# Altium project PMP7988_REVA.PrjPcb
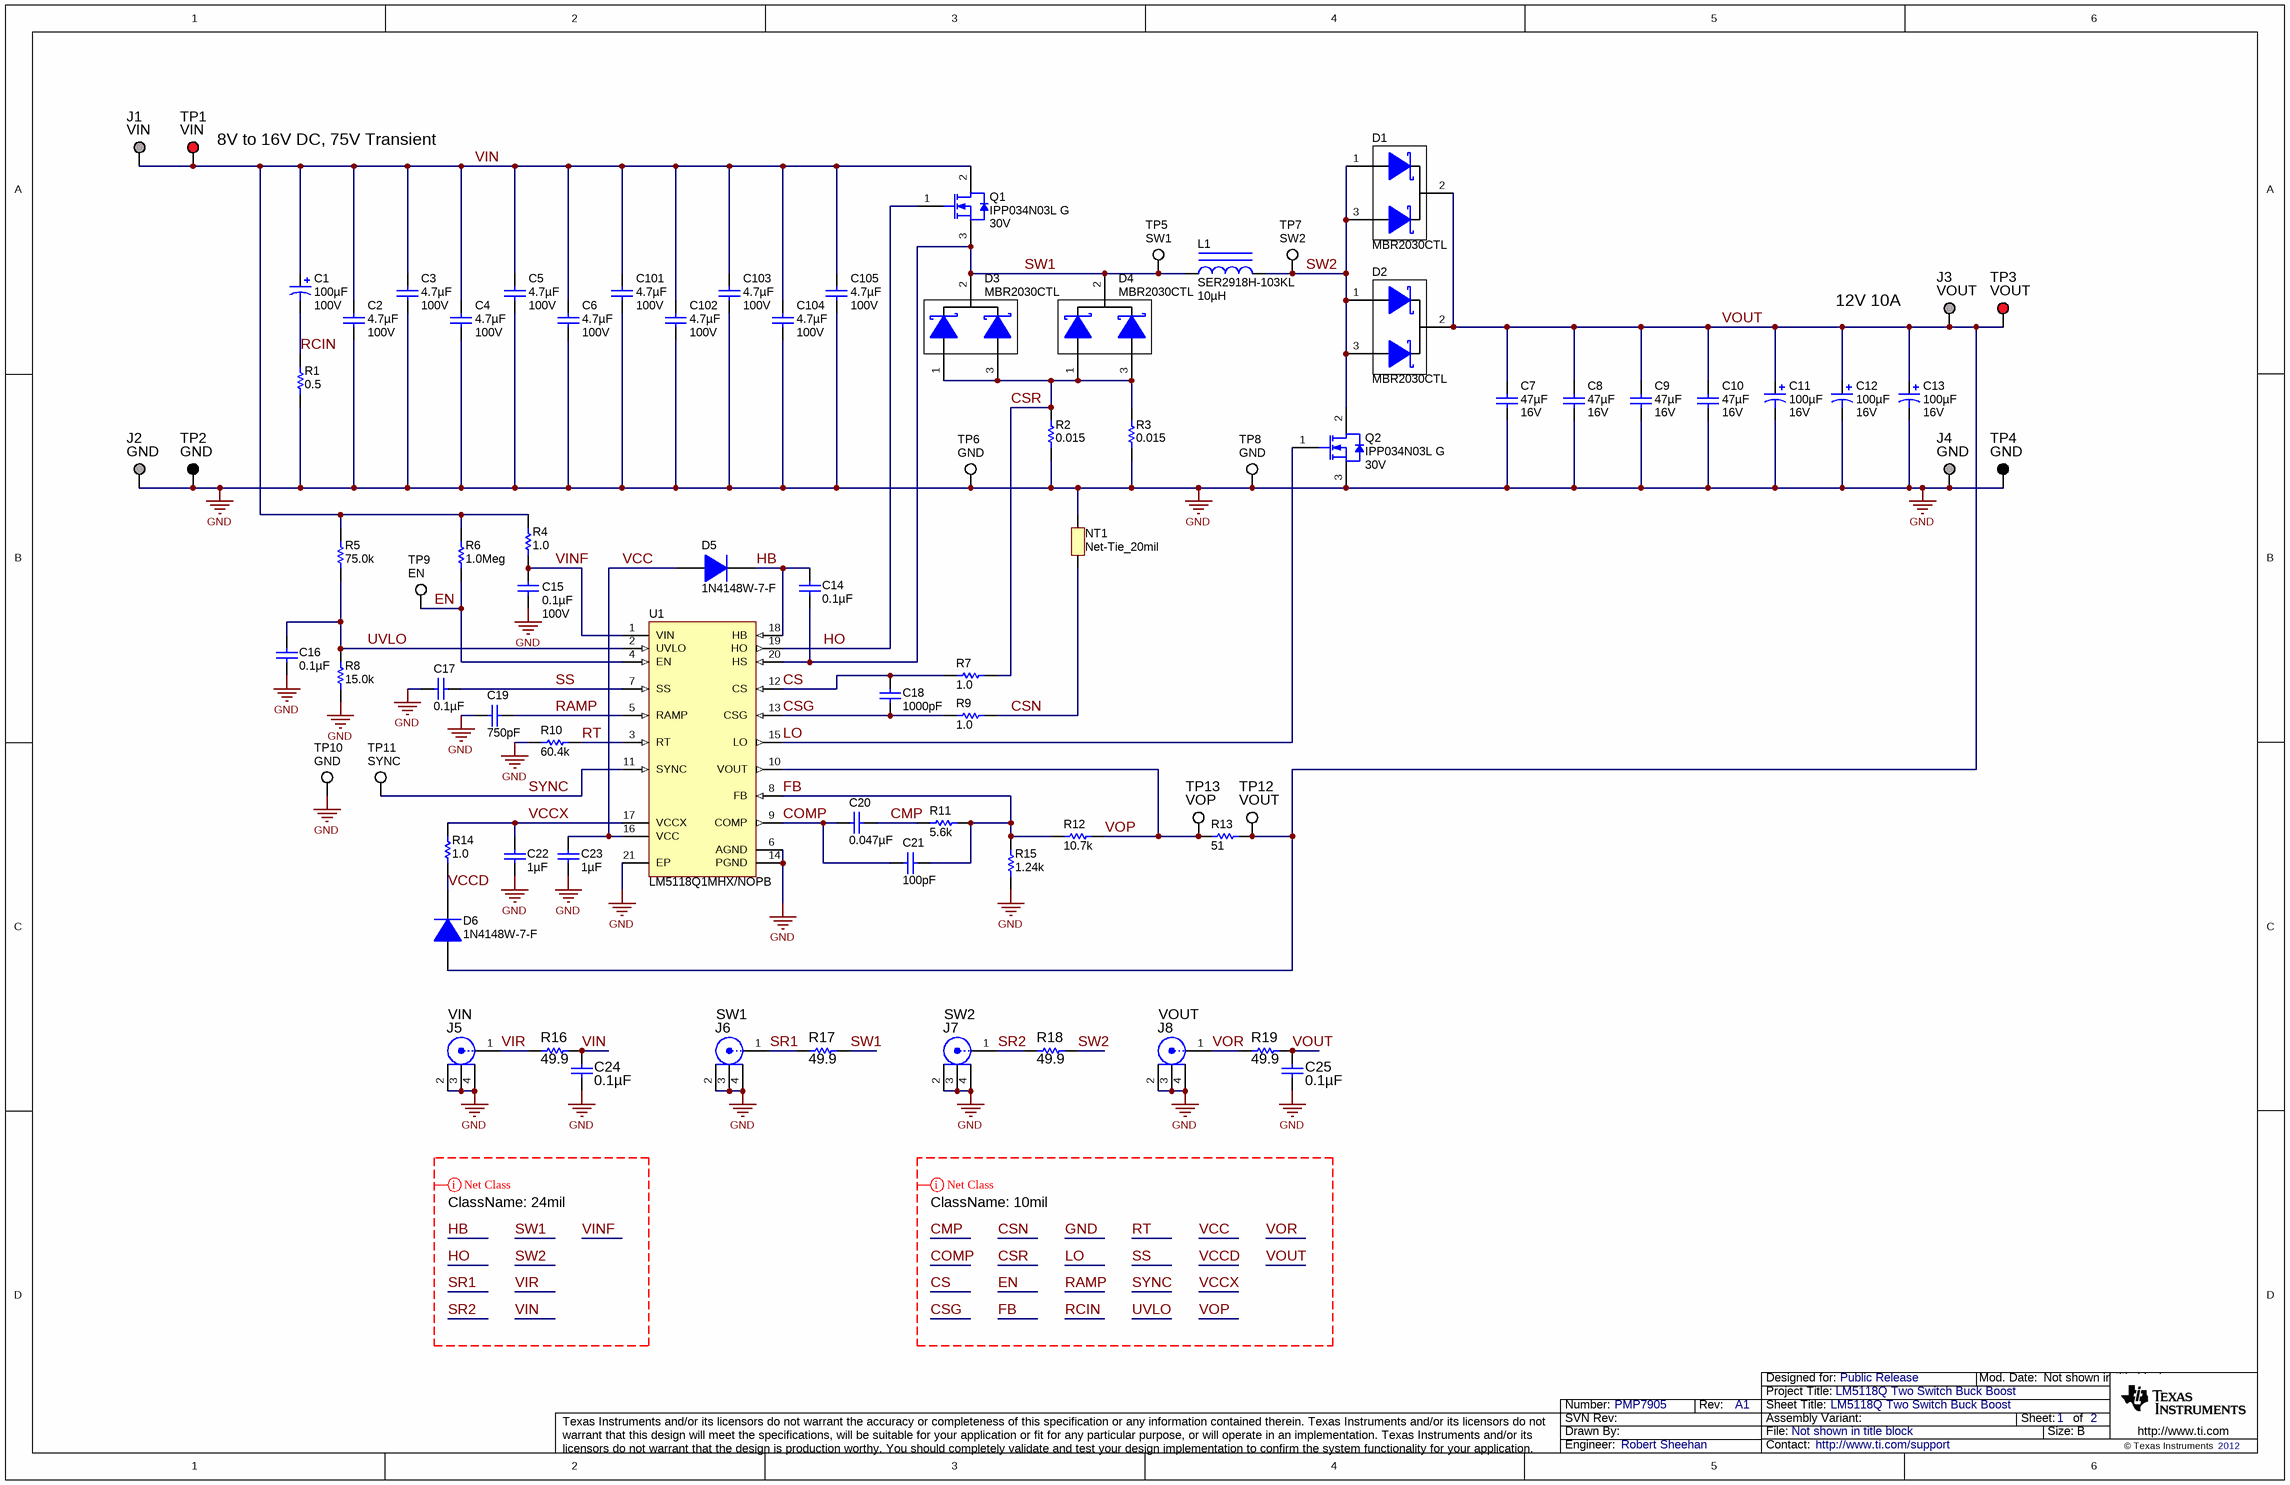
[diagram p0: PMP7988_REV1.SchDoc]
CopyrightYear: 2012; PCB_Layout: Robert Sheehan; PCB_Rev: A; PRJ_Customer: Public Release; PRJ_Engineer: Robert Sheehan; PRJ_Number: PMP7905; PRJ_Title: LM5118Q Two Switch Buck Boost; SCH_Rev: A1; TechSupport: http://www.ti.com/support
2 sheets, 118 parts. Net scope: global (net labels, ports and power ports of the same name join across sheets).
Board file: PMP7905_REVA.PcbDoc
Sheets:
  PMP7988_REV1.SchDoc
  PMP7988_REV1_Hardware.SchDoc

## Sheet PMP7988_REV1.SchDoc: LM5118Q Two Switch Buck Boost
size 431 x 279 mm; Date: Not shown in title block; ApprovedBy: Not shown in title block; CheckedBy: Not shown in title block; Author: Not shown in title block; CompanyName: Not shown in title block; Engineer: Not shown in title block; Organization: Not shown in title block; Address1: Not shown in title block; Address2: Not shown in title block; Address3: Not shown in title block; Address4: Not shown in title block; DocumentNumber: 1; Revision: Use project parameter SCH_Rev; SheetNumber: 1; SheetTotal: 2; PageSetup: Record=PageOptions|CenterHorizontal=True|CenterVertical=True|PrintScale=1.00|XCorrection=1.00|YCorrection=1.00|PrintKind=0|BorderSize=5000000|LeftOffset=0|BottomOffset=0|Orientation=2|PaperLength=1000|PaperWidth=1000|Scale=100|PaperSource=15|PrintQuality=600|MediaType=1|DitherType=10|PaperKind=Letter|PrintScaleMode=1

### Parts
C1  ValueDisplayed: 100µF  Value2: 100V  [SM_RADIAL_J16]  (hidden comment: EEV-FK2A101M)
C2  Value2: 100V  ValueDisplayed: 4.7µF  [1210]  (hidden comment: C3225X7S2A475M)
C3  Value2: 100V  ValueDisplayed: 4.7µF  [1210]  (hidden comment: C3225X7S2A475M)
C4  Value2: 100V  ValueDisplayed: 4.7µF  [1210]  (hidden comment: C3225X7S2A475M)
C5  Value2: 100V  ValueDisplayed: 4.7µF  [1210]  (hidden comment: C3225X7S2A475M)
C6  Value2: 100V  ValueDisplayed: 4.7µF  [1210]  (hidden comment: C3225X7S2A475M)
C7  ValueDisplayed: 47µF  Value2: 16V  [1210]  (hidden comment: GRM32ER61C476ME15L)
C8  ValueDisplayed: 47µF  Value2: 16V  [1210]  (hidden comment: GRM32ER61C476ME15L)
C9  ValueDisplayed: 47µF  Value2: 16V  [1210]  (hidden comment: GRM32ER61C476ME15L)
C10  ValueDisplayed: 47µF  Value2: 16V  [1210]  (hidden comment: GRM32ER61C476ME15L)
C11  ValueDisplayed: 100µF  Value2: 16V  [CAPSMT_62_F80]  (hidden comment: APXE160ARA101MF80G)
C12  ValueDisplayed: 100µF  Value2: 16V  [CAPSMT_62_F80]  (hidden comment: APXE160ARA101MF80G)
C13  ValueDisplayed: 100µF  Value2: 16V  [CAPSMT_62_F80]  (hidden comment: APXE160ARA101MF80G)
C14  ValueDisplayed: 0.1µF  [0805_HV]  (hidden comment: C2012X7R1E104K)
C15  ValueDisplayed: 0.1µF  Value2: 100V  [0805_HV]  (hidden comment: C2012X7R2A104K)
C16  ValueDisplayed: 0.1µF  [0805_HV]  (hidden comment: C2012X7R1E104K)
C17  ValueDisplayed: 0.1µF  [0805_HV]  (hidden comment: C2012X7R1E104K)
C18  ValueDisplayed: 1000pF  [0805_HV]  (hidden comment: GRM216R71E102KA01D)
C19  ValueDisplayed: 750pF  [0805_HV]  (hidden comment: GRM2165C1H751JA01D)
C20  ValueDisplayed: 0.047µF  [0805_HV]  (hidden comment: GRM219R71E473KA01D)
C21  ValueDisplayed: 100pF  [0805_HV]  (hidden comment: C2012C0G1H101J)
C22  ValueDisplayed: 1µF  [0805_HV]  (hidden comment: C2012X7R1E105K)
C23  ValueDisplayed: 1µF  [0805_HV]  (hidden comment: C2012X7R1E105K)
C24  ValueDisplayed: 0.1µF  [0805_HV]  (hidden comment: C2012X7R2A104K)
C25  ValueDisplayed: 0.1µF  [0805_HV]  (hidden comment: C2012X7R2A104K)
C101  Value2: 100V  ValueDisplayed: 4.7µF  [1210]  (hidden comment: C3225X7S2A475M)
C102  Value2: 100V  ValueDisplayed: 4.7µF  [1210]  (hidden comment: C3225X7S2A475M)
C103  Value2: 100V  ValueDisplayed: 4.7µF  [1210]  (hidden comment: C3225X7S2A475M)
C104  Value2: 100V  ValueDisplayed: 4.7µF  [1210]  (hidden comment: C3225X7S2A475M)
C105  Value2: 100V  ValueDisplayed: 4.7µF  [1210]  (hidden comment: C3225X7S2A475M)
D1  MBR2030CTL  [TO-220AB]
D2  MBR2030CTL  [TO-220AB]
D3  MBR2030CTL  [TO-220AB]
D4  MBR2030CTL  [TO-220AB]
D5  1N4148W-7-F  [SOD-123]
D6  1N4148W-7-F  [SOD-123]
J1  VIN  [Keystone1598-2]
J2  GND  [Keystone1598-2]
J3  VOUT  [Keystone1598-2]
J4  GND  [Keystone1598-2]
J5  VIN  [A-1JB]
J6  SW1  [A-1JB]
J7  SW2  [A-1JB]
J8  VOUT  [A-1JB]
L1  SER2918H-103KL  ValueDisplayed: 10µH  [SER2918]
NT1  Net-Tie_20mil  [Net-Tie_20mil]  (net tie, no BOM)
Q1  IPP034N03L G  value 30V  [TO-220AB]
Q2  IPP034N03L G  value 30V  [TO-220AB]
R1  value 0.5  [1206]  (hidden comment: CSR1206FKR500)
R2  value 0.015  [4527]  (hidden comment: WSR3R0150FEA)
R3  value 0.015  [4527]  (hidden comment: WSR3R0150FEA)
R4  value 1.0  [0805_HV]  (hidden comment: CRCW08051R00JNEA)
R5  value 75.0k  [0805_HV]  (hidden comment: CRCW080575K0FKEA)
R6  value 1.0Meg  [0805_HV]  (hidden comment: CRCW08051M00JNEA)
R7  value 1.0  [0805_HV]  (hidden comment: CRCW08051R00JNEA)
R8  value 15.0k  [0805_HV]  (hidden comment: CRCW080515K0FKEA)
R9  value 1.0  [0805_HV]  (hidden comment: CRCW08051R00JNEA)
R10  value 60.4k  [0805_HV]  (hidden comment: CRCW080560K4FKEA)
R11  value 5.6k  [0805_HV]  (hidden comment: CRCW08055K60JNEA)
R12  value 10.7k  [0805_HV]  (hidden comment: CRCW080510K7FKEA)
R13  value 51  [0805_HV]  (hidden comment: CRCW080551R0JNEA)
R14  value 1.0  [0805_HV]  (hidden comment: CRCW08051R00JNEA)
R15  value 1.24k  [0805_HV]  (hidden comment: CRCW08051K24FKEA)
R16  value 49.9  [0805_HV]  (hidden comment: CRCW080549R9FKEA)
R17  value 49.9  [0805_HV]  (hidden comment: CRCW080549R9FKEA)
R18  value 49.9  [0805_HV]  (hidden comment: CRCW080549R9FKEA)
R19  value 49.9  [0805_HV]  (hidden comment: CRCW080549R9FKEA)
TP1  VIN  [Keystone5010]
TP2  GND  [Keystone5011]
TP3  VOUT  [Keystone5010]
TP4  GND  [Keystone5011]
TP5  SW1  [Testpoint_Keystone_Miniature]
TP6  GND  [Testpoint_Keystone_Miniature]
TP7  SW2  [Testpoint_Keystone_Miniature]
TP8  GND  [Testpoint_Keystone_Miniature]
TP9  EN  [Testpoint_Keystone_Miniature]
TP10  GND  [Testpoint_Keystone_Miniature]
TP11  SYNC  [Testpoint_Keystone_Miniature]
TP12  VOUT  [Keystone5012]
TP13  VOP  [Keystone5012]
U1  LM5118Q1MHX/NOPB  [MXA20A_N]

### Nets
GND: C2.2 C3.2 C4.2 C5.2 C6.2 C7.2 C8.2 C9.2 C10.2 C11.2(-) C12.2(-) C13.2(-) C15.2 C16.2 C17.1 C19.1 C22.2 C23.2 C24.2 C25.2 C101.2 C102.2 C103.2 C104.2 C105.2 J2.1 J4.1 J5.2 J5.3 J5.4 J6.2 J6.3 J6.4 J7.2 J7.3 J7.4 J8.2 J8.3 J8.4 NT1.1 Q2.3(S) R1.1 R2.1 R3.1 R8.1 R10.2 R15.1 TP2.1 TP4.1 TP6.1 TP8.1 TP10.1 U1.6(AGND) U1.14(PGND) U1.21(EP)
CMP: C20.1 R11.1
COMP: C20.2 C21.2 U1.9(COMP)
CS: C18.1 R7.2 U1.12(CS)
CSG: C18.2 R9.2 U1.13(CSG)
CSN: NT1.2 R9.1
CSR: D3.1(A) D3.3(A) D4.1(A) D4.3(A) R2.2 R3.2 R7.1
EN: R6.1 TP9.1 U1.4(EN)
FB: C21.1 R11.2 R12.1 R15.2 U1.8(FB)
HB: C14.1 D5.1(K) U1.18(HB)
HO: Q1.1(G) U1.19(HO)
LO: Q2.1(G) U1.15(LO)
RAMP: C19.2 U1.5(RAMP)
RCIN: C1.2(-) R1.2
RT: R10.1 U1.3(RT)
SR1: J6.1 R17.1
SR2: J7.1 R18.1
SS: C17.2 U1.7(SS)
SW1: C14.2 D3.2(K) D4.2(K) L1.2 Q1.3(S) R17.2 TP5.1 U1.20(HS)
SW2: D1.1(A) D1.3(A) D2.1(A) D2.3(A) L1.1 Q2.2(D) R18.2 TP7.1
SYNC: TP11.1 U1.11(SYNC)
UVLO: C16.1 R5.1 R8.2 U1.2(UVLO)
VCC: C23.1 D5.2(A) U1.16(VCC)
VCCD: D6.1(K) R14.2
VCCX: C22.1 R14.1 U1.17(VCCX)
VIN: C1.1(+) C2.1 C3.1 C4.1 C5.1 C6.1 C24.1 C101.1 C102.1 C103.1 C104.1 C105.1 J1.1 Q1.2(D) R4.1 R5.2 R6.2 R16.2 TP1.1
VINF: C15.1 R4.2 U1.1(VIN)
VIR: J5.1 R16.1
VOP: R12.2 R13.1 TP13.1 U1.10(VOUT)
VOR: J8.1 R19.1
VOUT: C7.1 C8.1 C9.1 C10.1 C11.1(+) C12.1(+) C13.1(+) C25.1 D1.2(K) D2.2(K) D6.2(A) J3.1 R13.2 R19.2 TP3.1 TP12.1

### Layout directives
net class 24mil: HB, HO, SR1, SR2, SW1, SW2, VIN, VINF, VIR
net class 10mil: CMP, COMP, CS, CSG, CSN, CSR, EN, FB, GND, LO, RAMP, RCIN, RT, SS, SYNC, UVLO, VCC, VCCD, VCCX, VOP, VOR, VOUT

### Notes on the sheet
- (near TP1) 8V to 16V DC, 75V Transient
- (near J3) 12V 10A

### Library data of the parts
C1 = EEV-FK2A101M: CAP, AL, 100uF, 100V, +/-20%, 0.17 ohm, SMD; Manufacturer: Panasonic; Polarized: Y; CompType: Capacitor; U/M: EA; Cap_F: 0.0001; Tolerance_%: 20; VDC_V: 100; ESR_Ohm: 0.17; IRMS_A: 0.793; TaMin_C: -55; TaMax_C: 105; Cap_Case: J16
C2-C6 C101-C105 = C3225X7S2A475M: CAP, CERM, 4.7uF, 100V, +/-20%, X7S, 1210; Manufacturer: TDK; Polarized: N; CompType: Capacitor; U/M: EA; Cap_F: 0.0000047; Tolerance_%: 20; VDC_V: 100; TaMin_C: -55; TaMax_C: 125
C7-C10 = GRM32ER61C476ME15L: CAP, CERM, 47uF, 16V, +/-20%, X5R, 1210; Manufacturer: MuRata; Polarized: N; CompType: Capacitor; U/M: EA; Cap_F: 0.000047; Tolerance_%: 20; ESR_Ohm: 0.002; Value1: 0.002 ohm; VDC_V: 16; TaMin_C: -55; TaMax_C: 85
C11-C13 = APXE160ARA101MF80G: CAP, AL, 100uF, 16V, +/-20%, 0.024 ohm, SMD; Manufacturer: Nippon Chemi-Con; Polarized: Y; CompType: Capacitor; U/M: EA; Cap_F: 0.0001; Tolerance_%: 20; VDC_V: 16; ESR_Ohm: 0.024; IRMS_A: 2.7; TaMin_C: -55; TaMax_C: 105; Cap_Case: F80
C14 C16 C17 = C2012X7R1E104K: CAP, CERM, 0.1uF, 25V, +/-10%, X7R, 0805; Manufacturer: TDK; Polarized: N; CompType: Capacitor; U/M: EA; Cap_F: 0.0000001; Tolerance_%: 10; VDC_V: 25; TaMin_C: -55; TaMax_C: 125; Cap_Case: 0805
C15 = C2012X7R2A104K: CAP, CERM, 0.1uF, 100V, +/-10%, X7R, 0805; Manufacturer: TDK; Polarized: N; CompType: Capacitor; U/M: EA; Cap_F: 0.0000001; Tolerance_%: 10; ESR_Ohm: 0.0158; Value1: 0.0158 ohm; VDC_V: 100; TaMin_C: -55; TaMax_C: 125; Cap_Case: 0805
C18 = GRM216R71E102KA01D: CAP, CERM, 1000pF, 25V, +/-10%, X7R, 0805; Manufacturer: MuRata; Polarized: N; CompType: Capacitor; U/M: EA; Cap_F: 0.000000001; Tolerance_%: 10; VDC_V: 25; TaMin_C: -55; TaMax_C: 125; Cap_Case: 0805
C19 = GRM2165C1H751JA01D: CAP, CERM, 750pF, 50V, +/-5%, C0G/NP0, 0805; Manufacturer: MuRata; Polarized: N; CompType: Capacitor; U/M: EA; Cap_F: 0.00000000075; Tolerance_%: 5; VDC_V: 50; TaMin_C: -55; TaMax_C: 125; Cap_Case: 0805
C20 = GRM219R71E473KA01D: CAP, CERM, 0.047uF, 25V, +/-10%, X7R, 0805; Manufacturer: MuRata; Polarized: N; CompType: Capacitor; U/M: EA; Cap_F: 0.000000047; Tolerance_%: 10; VDC_V: 25; TaMin_C: -55; TaMax_C: 125; Cap_Case: 0805
C21 = C2012C0G1H101J: CAP, CERM, 100pF, 50V, +/-5%, C0G/NP0, 0805; Manufacturer: TDK; Polarized: N; CompType: Capacitor; U/M: EA; Cap_F: 0.0000000001; Tolerance_%: 5; VDC_V: 50; TaMin_C: -55; TaMax_C: 125; Cap_Case: 0805
C22 C23 = C2012X7R1E105K: CAP, CERM, 1uF, 25V, +/-10%, X7R, 0805; Manufacturer: TDK; Polarized: N; CompType: Capacitor; U/M: EA; Cap_F: 0.000001; Tolerance_%: 10; ESR_Ohm: 0.0075; Value1: 0.0075 ohm; VDC_V: 25; TaMin_C: -55; TaMax_C: 125; Cap_Case: 0805
C24 C25 = C2012X7R2A104K: CAP, CERM, 0.1uF, 100V, +/-10%, X7R, 0805; Manufacturer: TDK; Cap_Case: 0805; ESR_Ohm: 0.0158; Polarized: N; TaMax_C: 125; TaMin_C: -55; Tolerance_%: 10; VDC_V: 100; Cap_F: 0.0000001; CompType: Capacitor; Value1: 0.0158 ohm; U/M: EA
D1-D4 = MBR2030CTL: Diode, Schottky, 30V, 20A, TO-220; Manufacturer: On Semiconductor; Value: 0.52V; U/M: EA; Vf_V: 0.52; Io_A: 15; Vr_V: 30; TJmax_C: 150; RJC_CperW: 3
D5 D6 = 1N4148W-7-F: Diode, Ultrafast, 100V, 0.15A, SOD-123; Manufacturer: Diodes Inc.; U/M: EA; Vf_V: 1.25; Io_A: 0.15; Vr_V: 100; TJmax_C: 150; Value: 1.25V
J1-J4 = 1598-2: Terminal, Turret, TH, Triple; Manufacturer: Keystone; Alternate PartNumber: Equivalent; Alternate Manufacturer: Any; CompType: Turret Terminal; U/M: EA
J5-J8 = A-1JB: Connector, RF Jack, Vertical, Gold, SMD; Manufacturer: Amphenol; SymbolCreator: crossc; U/M: EA; Value: 50 ohm
L1 = SER2918H-103KL: Inductor, Shielded E Core, Ferrite, 10uH, 28A, 0.0026 ohm, SMD; Manufacturer: Coilcraft; Ind_H: 10.0E-6; Imax_A: 28; Irms: 28A @ 40C rise; Isat: 32.1A @ 30% inductance drop; DCR_ohm: 0.0026; U/M: EA
NT1 = Net-Tie_20mil: Single point connection between nets.; SymbolCreator: crossc
Q1 Q2 = IPP034N03L G: MOSFET, N-CH, 30V, 80A, TO-220; Manufacturer: Infineon Technologies; Alternate Manufacturer: None; U/M: EA; ChType: N; VdsMax_V: 30; Value1: 0.0034 ohm; Rdson45_Ohm: 0.0038; Value2: 25 nC; QgTyp_nC: 25; Vgs_V: 20; IdsMax_A: 120
R1 = CSR1206FKR500: RES, 0.5 ohm, 1%, 0.5W, 1206; Manufacturer: Stackpole Electronics Inc; CompType: Resistor; Value_Code: R500; Tolerance_%: 1; TempCo: 100 ppm/C; U/M: EA
R2 R3 = WSR3R0150FEA: RES, 0.015 ohm, 1%, 3W, 4527; Manufacturer: Vishay-Dale; CompType: Resistor; Value_Code: R015; Tolerance_%: 1; Power_W: 3; TempCo: 75 ppm/C; EIA_Code: E96; U/M: EA
R4 R7 R9 R14 = CRCW08051R00JNEA: RES, 1.0 ohm, 5%, 0.125W, 0805; Manufacturer: Vishay-Dale; CompType: Resistor; Res_ohm: 1; Value_Code: 1R00; Tolerance_%: 5; Power_W: 0.125; VDC_V: 150; TempCo: 200 ppm/C; EIA_Code: E24; U/M: EA
R5 = CRCW080575K0FKEA: RES, 75.0k ohm, 1%, 0.125W, 0805; Manufacturer: Vishay-Dale; CompType: Resistor; Res_ohm: 75000; Value_Code: 75k0; Tolerance_%: 1; Power_W: 0.125; VDC_V: 150; TempCo: 100 ppm/C; EIA_Code: E96; U/M: EA
R6 = CRCW08051M00JNEA: RES, 1.0Meg ohm, 5%, 0.125W, 0805; Manufacturer: Vishay-Dale; CompType: Resistor; Res_ohm: 1000000; Value_Code: 1M00; Tolerance_%: 5; Power_W: 0.125; VDC_V: 150; TempCo: 200 ppm/C; EIA_Code: E24; U/M: EA
R8 = CRCW080515K0FKEA: RES, 15.0k ohm, 1%, 0.125W, 0805; Manufacturer: Vishay-Dale; CompType: Resistor; Res_ohm: 15000; Value_Code: 15k0; Tolerance_%: 1; Power_W: 0.125; VDC_V: 150; TempCo: 100 ppm/C; EIA_Code: E96; U/M: EA
R10 = CRCW080560K4FKEA: RES, 60.4k ohm, 1%, 0.125W, 0805; Manufacturer: Vishay-Dale; CompType: Resistor; Res_ohm: 60400; Value_Code: 60k4; Tolerance_%: 1; Power_W: 0.125; VDC_V: 150; TempCo: 100 ppm/C; EIA_Code: E96; U/M: EA
R11 = CRCW08055K60JNEA: RES, 5.6k ohm, 5%, 0.125W, 0805; Manufacturer: Vishay-Dale; CompType: Resistor; Res_ohm: 5600; Value_Code: 5k60; Tolerance_%: 5; Power_W: 0.125; VDC_V: 150; TempCo: 200 ppm/C; EIA_Code: E24; U/M: EA
R12 = CRCW080510K7FKEA: RES, 10.7k ohm, 1%, 0.125W, 0805; Manufacturer: Vishay-Dale; CompType: Resistor; Res_ohm: 10700; Value_Code: 10k7; Tolerance_%: 1; Power_W: 0.125; VDC_V: 150; TempCo: 100 ppm/C; EIA_Code: E96; U/M: EA
R13 = CRCW080551R0JNEA: RES, 51 ohm, 5%, 0.125W, 0805; Manufacturer: Vishay-Dale; CompType: Resistor; Value_Code: 51R0; Tolerance_%: 5; Power_W: 0.125; VDC_V: 150; TempCo: 200 ppm/C; EIA_Code: E24; U/M: EA
R15 = CRCW08051K24FKEA: RES, 1.24k ohm, 1%, 0.125W, 0805; Manufacturer: Vishay-Dale; CompType: Resistor; Res_ohm: 1240; Value_Code: 1k24; Tolerance_%: 1; Power_W: 0.125; VDC_V: 150; TempCo: 100 ppm/C; EIA_Code: E96; U/M: EA
R16-R19 = CRCW080549R9FKEA: RES, 49.9 ohm, 1%, 0.125W, 0805; Manufacturer: Vishay-Dale; Alternate PartNumber: Equivalent; Alternate Manufacturer: Any; CompType: Resistor; Value_Code: 49R9; Tolerance_%: 1; Power_W: 0.125; VDC_V: 150; TempCo: 100 ppm/C; EIA_Code: E96; U/M: EA
TP1 TP3 = 5010: Test Point, TH, Multipurpose, Red; Manufacturer: Keystone; Alternate Manufacturer: Any; Alternate PartNumber: Equivalent; CompType: Test Point Loop; U/M: EA
TP2 TP4 = 5011: Test Point, TH, Multipurpose, Black; Manufacturer: Keystone; Alternate Manufacturer: Any; Alternate PartNumber: Equivalent; CompType: Test Point Loop; U/M: EA
TP5-TP11 = 5015: Test Point, SMT, Miniature; Manufacturer: Keystone; CompType: Test Point Loop; U/M: EA
TP12 TP13 = 5012: Test Point, TH, Multipurpose, White; Manufacturer: Keystone; Alternate Manufacturer: Any; Alternate PartNumber: Equivalent; CompType: Test Point Loop; U/M: EA
U1 = LM5118Q1MHX/NOPB: Wide Voltage Range Buck-Boost Controller, 20-pin TSSOP-EP, Pb-Free; Manufacturer: National Semiconductor; PackageTopMarking: NSUZXYTT*LM5118*Q1MH; PowerWise: N; CompType: Switcher

## Sheet PMP7988_REV1_Hardware.SchDoc: LM5118Q Two Switch Buck Boost Hardware
size 431 x 279 mm; Date: Not shown in title block; ApprovedBy: Not shown in title block; CheckedBy: Not shown in title block; Author: Not shown in title block; CompanyName: Not shown in title block; Engineer: Not shown in title block; Organization: Not shown in title block; Address1: Not shown in title block; Address2: Not shown in title block; Address3: Not shown in title block; Address4: Not shown in title block; DocumentNumber: 2; Revision: Use project parameter SCH_Rev; SheetNumber: 2; SheetTotal: 2; PageSetup: Record=PageOptions|CenterHorizontal=True|CenterVertical=True|PrintScale=1.00|XCorrection=1.00|YCorrection=1.00|PrintKind=0|BorderSize=5000000|LeftOffset=0|BottomOffset=0|Orientation=2|PaperLength=1000|PaperWidth=1000|Scale=100|PaperSource=15|PrintQuality=600|MediaType=1|DitherType=10|PaperKind=Letter|PrintScaleMode=1
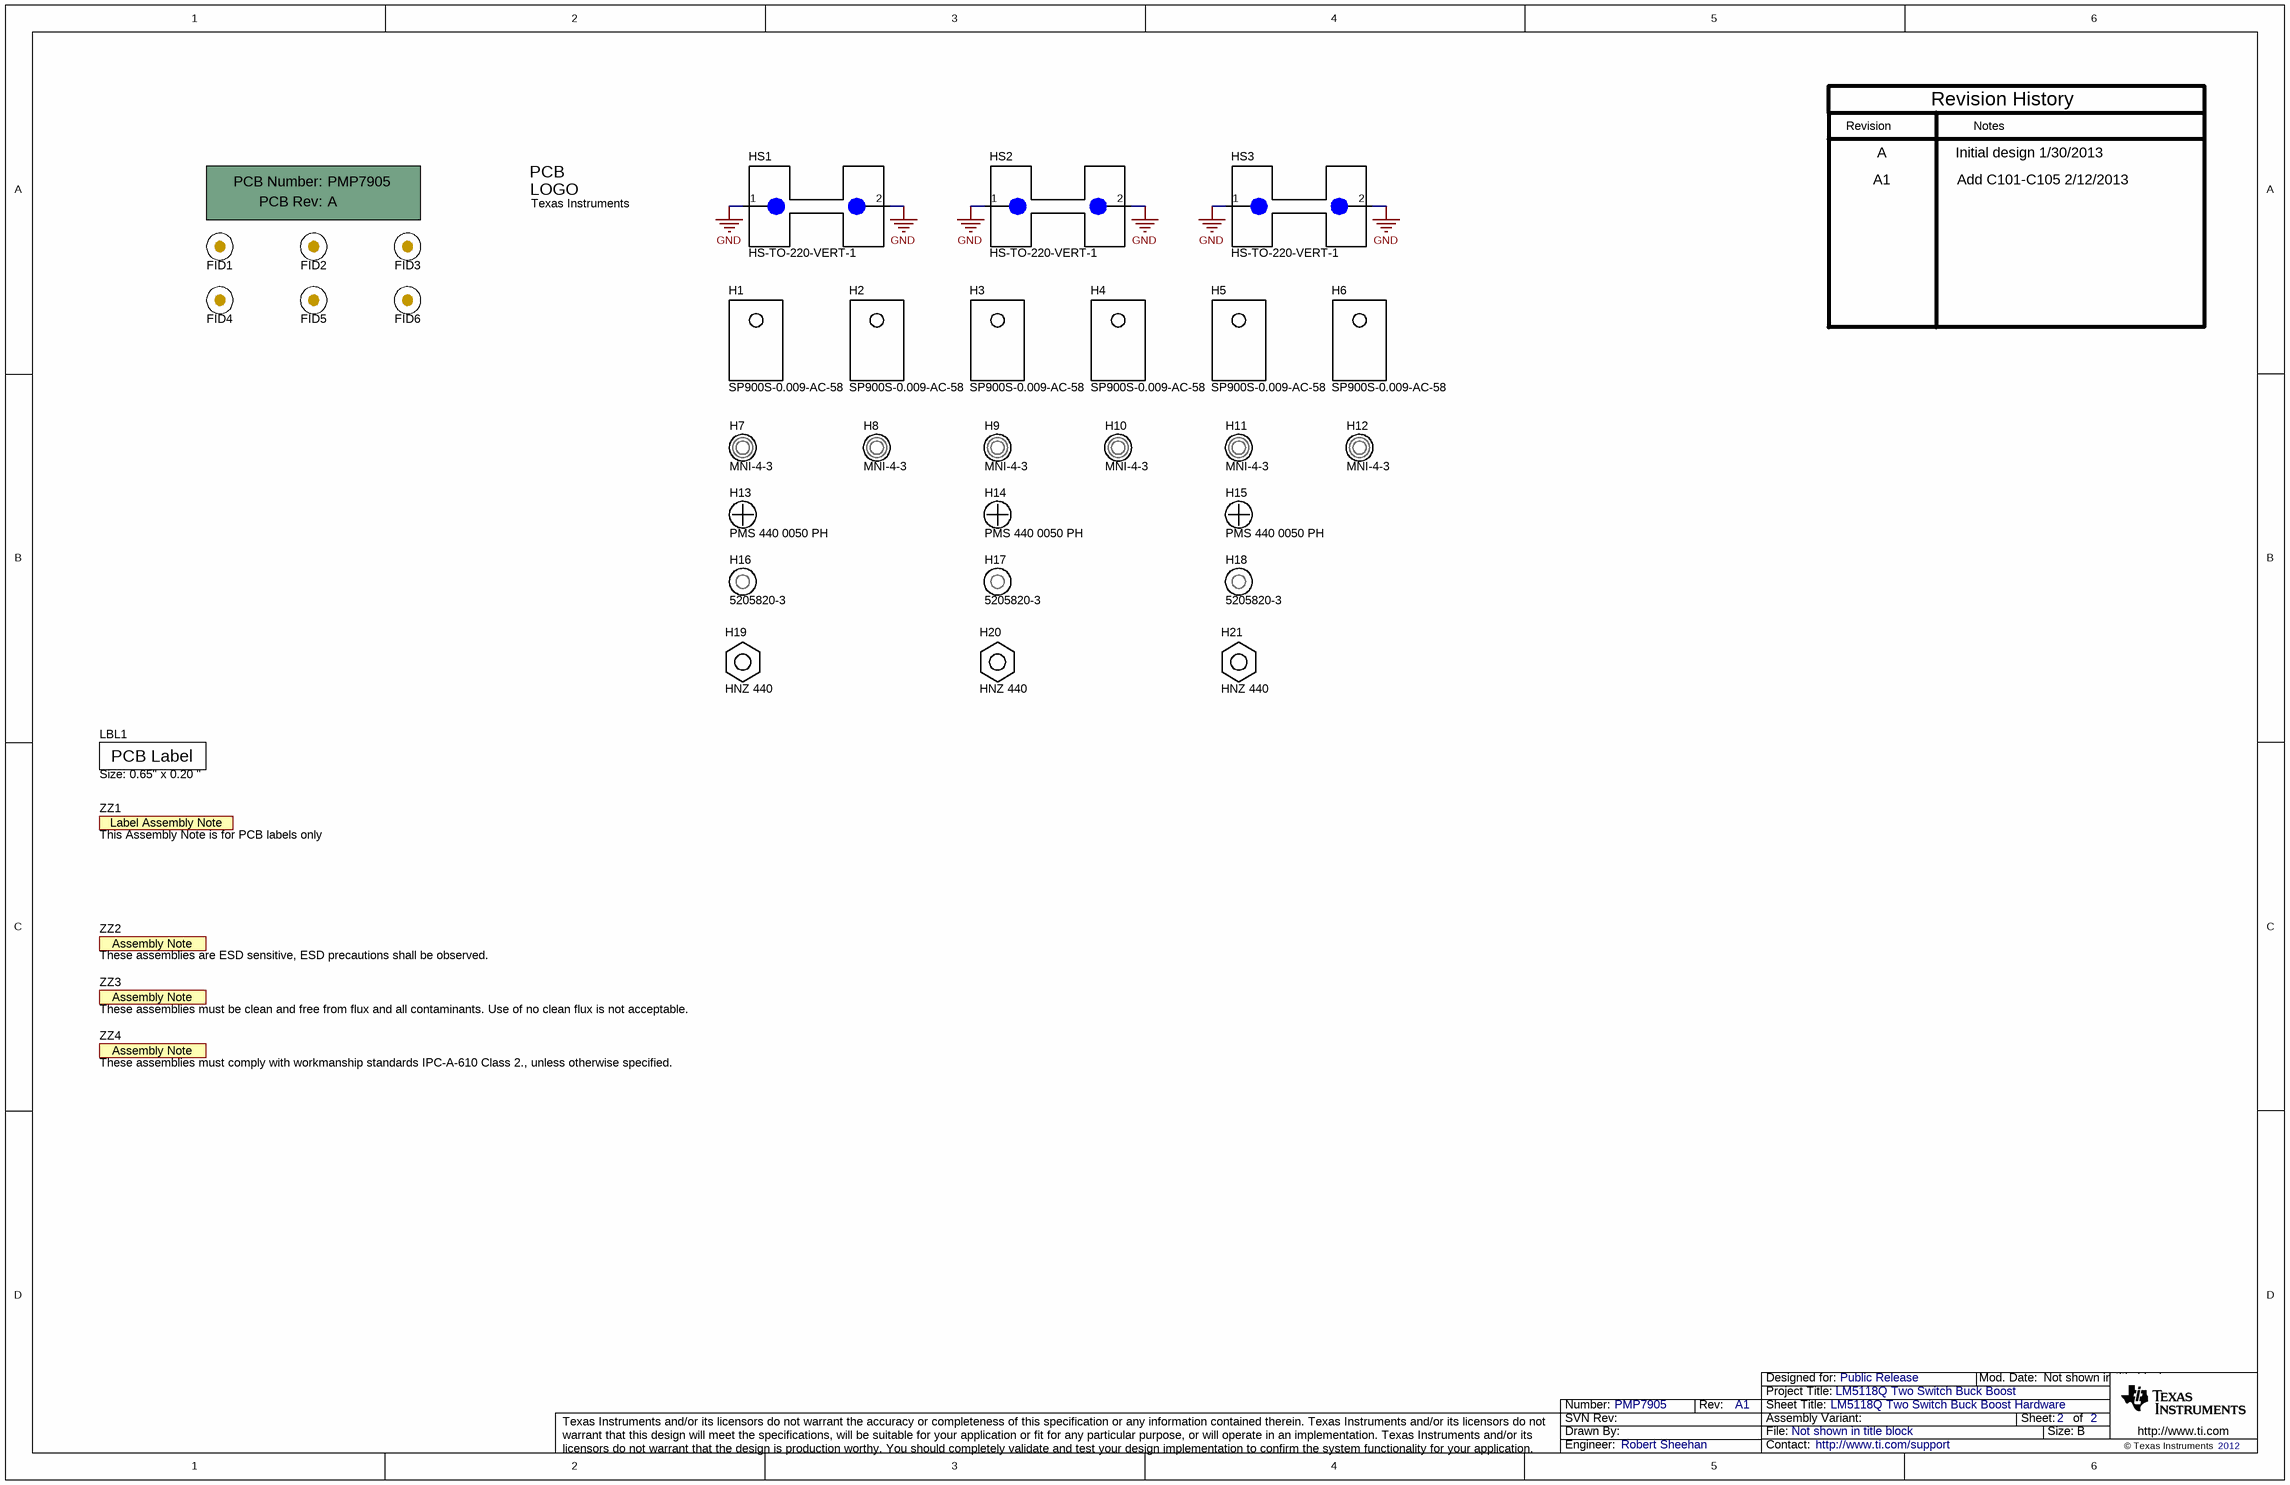
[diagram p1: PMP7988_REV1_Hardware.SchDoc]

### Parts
!PCB1  Printed Circuit Board  (value not drawn)  (mechanical)
FID1  Fiducial  [Fiducial10-20_TopLayerKeepOutOnly]  (value not drawn)
FID2  Fiducial  [Fiducial10-20_TopLayerKeepOutOnly]  (value not drawn)
FID3  Fiducial  [Fiducial10-20_TopLayerKeepOutOnly]  (value not drawn)
FID4  Fiducial  [Fiducial10-20_TopLayerKeepOutOnly]  (value not drawn)
FID5  Fiducial  [Fiducial10-20_TopLayerKeepOutOnly]  (value not drawn)
FID6  Fiducial  [Fiducial10-20_TopLayerKeepOutOnly]  (value not drawn)
H1  SP900S-0.009-AC-58
H2  SP900S-0.009-AC-58
H3  SP900S-0.009-AC-58
H4  SP900S-0.009-AC-58
H5  SP900S-0.009-AC-58
H6  SP900S-0.009-AC-58
H7  MNI-4-3
H8  MNI-4-3
H9  MNI-4-3
H10  MNI-4-3
H11  MNI-4-3
H12  MNI-4-3
H13  PMS 440 0050 PH
H14  PMS 440 0050 PH
H15  PMS 440 0050 PH
H16  5205820-3
H17  5205820-3
H18  5205820-3
H19  HNZ 440
H20  HNZ 440
H21  HNZ 440
HS1  HS-TO-220-VERT-1  [HS-TO-220-VERT-1]
HS2  HS-TO-220-VERT-1  [HS-TO-220-VERT-1]
HS3  HS-TO-220-VERT-1  [HS-TO-220-VERT-1]
LBL1  Size: 0.65" x 0.20 "  [Label_650x200]
Logo1  Texas Instruments  [TI_Stacked_SolderMask_Small]  (no BOM)
ZZ1  This Assembly Note is for PCB labels only  [AssemblyNoteLabel]  (no BOM)
ZZ2  These assemblies are ESD sensitive, ESD precautions shall be observed.  [AssemblyNote]  (no BOM)
ZZ3  These assemblies must be clean and free from flux and all contaminants. Use of no clean flux is not acceptable.  [AssemblyNote]  (no BOM)
ZZ4  These assemblies must comply with workmanship standards IPC-A-610 Class 2., unless otherwise specified.  [AssemblyNote]  (no BOM)

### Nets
GND: HS1.1 HS1.2 HS2.1 HS2.2 HS3.1 HS3.2

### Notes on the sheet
- Revision History
- Revision
- A
- Notes
- Initial design 1/30/2013
- A1
- Add C101-C105 2/12/2013

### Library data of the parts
!PCB1 = PCB: Manufacturer: Any; PartNumber: PMP7905; SymbolCreator: a0412235
FID1-FID6 = Fiducial: Fiducial mark.  There is nothing to buy or mount.; SymbolCreator: codlsc
H1-H6 = Sil-Pad-TO-220: THERM PAD TO-220 W/ADH .009" SP9; Manufacturer: Bergquist; CompType: Hardware; U/M: EA; Shape: Rectangular; Outline: 19.05mm x 12.70mm; Adhesive: Adhesive - One Side; Backing, Carrier: Fiberglass; Thermal Resistivity: 0.61°C/W; Thermal Conductivity: 1.6 W/m-K
H7-H12 = Shoulder-Washer-TO-220: WASHER SHOULDER #4 NYLON 25/PK; Manufacturer: Richco Plastic Co; CompType: Hardware
H13-H15 = Screw#4-40x1/2: Machine Screw, Round, #4-40 x 1/2 Steel, Philips panhead; Manufacturer: B&F Fastener Supply; CompType: Hardware; U/M: EA; Description: MACHINE SCREW PAN PHILLIPS 4-40; Drive Type: Phillips; Thread Size: 4-40; Head Height: 0.075" (1.91mm); Plating: Zinc
H16-H18 = Washer#4: WASHER FLAT #4 STEEL; Manufacturer: TE Connectivity; CompType: Hardware; Plating: Zinc, Clear Chromate
H19-H21 = Nut#4-40: HEX NUT 1/4" 4-40 100/PK; Manufacturer: B&F Fastener Supply; CompType: Hardware; Plating: Zinc
HS1-HS3 = HS-TO-220-VERT-1: Heat Sink TO-220 Vertical 1 Inch; Manufacturer: AAVID Thermalloy; PartNumber: 529702B02500G; SymbolCreator: crossc; CompType: Hardware; U/M: EA
LBL1 = THT-14-423-10: Thermal Transfer Printable Labels, 0.650" W x 0.200" H - 10,000 per roll; Manufacturer: Brady; SymbolCreator: a0412235; CompType: Label
Logo1 = TI_Logo: Texas Instrument Corporate Signature; SymbolCreator: codlsc
ZZ1 = AssemblyNoteLabel: SymbolCreator: a0412235
ZZ2-ZZ4 = AssemblyNote: SymbolCreator: codlsc

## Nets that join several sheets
GND: PMP7988_REV1 (55 pins), PMP7988_REV1_Hardware (6 pins)

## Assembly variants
001: all parts fitted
